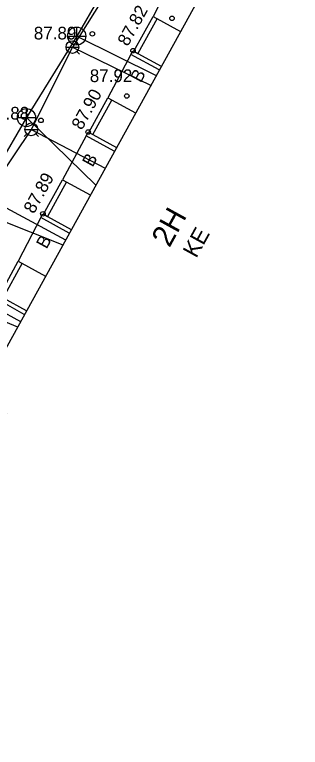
# Model space of a CAD drawing. Extents: x 648748 to 649126, y 6457789 to 6458252.
# Drawn here: x 648855.94 to 648871.67, y 6458013.84 to 6458054.26 of the extents above; entities that cross this region are included whole.
import ezdxf

# ---------------------------------------------------------------- set-up
doc = ezdxf.new("R2010")
doc.units = 0
for name, color, linetype in [('HOONE', 7, 'Continuous'), ('HOONEDET', 7, 'Continuous'), ('KKAEV', 7, 'Continuous'), ('KORGUS-EH2000', 7, 'Continuous'), ('KTRASS', 7, 'Continuous'), ('TEE', 7, 'Continuous'), ('VKAEV', 7, 'Continuous'), ('VTRASS', 7, 'Continuous')]:
    doc.layers.add(name, color=color, linetype=linetype)

msp = doc.modelspace()

# ---------------------------------------------------------------- linework, layer by layer
at = {"layer": 'HOONE'}
for points in [[(648871.67, 6458059.037), (648869.02, 6458060.498), (648853.919, 6458033.105), (648855.485, 6458032.242), (648840.687, 6458005.398), (648842.333, 6458004.491), (648827.567, 6457977.705), (648832.374, 6457975.097)], [(648863.896, 6458051.204), (648862.339, 6458052.062), (648862.452, 6458052.267), (648862.503, 6458052.239), (648863.562, 6458054.16), (648865.068, 6458053.33)], [(648861.425, 6458046.721), (648859.873, 6458047.576), (648859.986, 6458047.781), (648860.024, 6458047.76), (648861.074, 6458049.666), (648862.589, 6458048.832)], [(648858.938, 6458042.209), (648857.38, 6458043.068), (648857.493, 6458043.273), (648857.534, 6458043.25), (648858.581, 6458045.15), (648860.098, 6458044.313)], [(648856.466, 6458037.725), (648854.897, 6458038.59), (648855.01, 6458038.795), (648855.085, 6458038.754), (648856.136, 6458040.661), (648857.631, 6458039.837)]]:
    msp.add_lwpolyline(points, dxfattribs=at)
at = {"layer": 'HOONEDET'}
for p, q in [((648863.781, 6458054.039), (648862.722, 6458052.118)), ((648860.243, 6458047.64), (648861.293, 6458049.546)), ((648858.8, 6458045.029), (648857.753, 6458043.13)), ((648856.355, 6458040.541), (648855.304, 6458038.633))]:
    msp.add_line(p, q, dxfattribs=at)
for points in [[(648862.503, 6458052.239), (648862.722, 6458052.118), (648864.009, 6458051.408)], [(648860.024, 6458047.76), (648860.243, 6458047.64), (648861.538, 6458046.925)], [(648857.534, 6458043.25), (648857.753, 6458043.13), (648859.051, 6458042.414)], [(648855.085, 6458038.754), (648855.304, 6458038.633), (648856.579, 6458037.93)]]:
    msp.add_lwpolyline(points, dxfattribs=at)
at = {"layer": 'KKAEV'}
for p, q in [((648859.355, 6458052.572), (648859.355, 6458053.572)), ((648858.855, 6458053.072), (648859.855, 6458053.072)), ((648856.587, 6458048.075), (648856.587, 6458049.075)), ((648856.087, 6458048.575), (648857.087, 6458048.575))]:
    msp.add_line(p, q, dxfattribs=at)
for centre in [(648859.355, 6458053.072), (648856.587, 6458048.575)]:
    msp.add_circle(centre, 0.5, dxfattribs=at)
at = {"layer": 'KORGUS-EH2000'}
for centre in [(648864.603, 6458054.053), (648860.215, 6458053.2), (648862.452, 6458052.267), (648862.112, 6458049.769), (648857.384, 6458048.423), (648859.986, 6458047.781), (648857.493, 6458043.273)]:
    msp.add_circle(centre, 0.125, dxfattribs=at)
at = {"layer": 'KTRASS'}
for p, q in [((648861.722, 6458057.158), (648859.355, 6458053.072)), ((648859.355, 6458053.072), (648856.587, 6458048.575)), ((648859.355, 6458053.072), (648863.723, 6458050.903)), ((648856.587, 6458048.575), (648854.114, 6458044.329)), ((648856.587, 6458048.575), (648860.4, 6458044.844)), ((648854.114, 6458044.329), (648858.745, 6458041.841)), ((648851.641, 6458039.895), (648856.255, 6458037.322))]:
    msp.add_line(p, q, dxfattribs=at)
at = {"layer": 'TEE'}
for p, q in [((648864.782, 6458056.52), (648863.562, 6458054.16)), ((648862.339, 6458052.062), (648861.074, 6458049.666)), ((648859.873, 6458047.576), (648858.581, 6458045.15)), ((648857.38, 6458043.068), (648856.136, 6458040.661))]:
    msp.add_line(p, q, dxfattribs=at)
at = {"layer": 'VKAEV'}
for p, q in [((648858.871, 6458052.221), (648858.732, 6458052.082)), ((648858.769, 6458052.469), (648859.469, 6458052.469)), ((648859.366, 6458052.221), (648859.506, 6458052.082)), ((648856.505, 6458047.93), (648857.205, 6458047.93)), ((648856.608, 6458047.683), (648856.468, 6458047.543)), ((648857.103, 6458047.683), (648857.242, 6458047.543))]:
    msp.add_line(p, q, dxfattribs=at)
for centre in [(648859.119, 6458052.469), (648856.855, 6458047.93)]:
    msp.add_circle(centre, 0.35, dxfattribs=at)
at = {"layer": 'VTRASS'}
for p, q in [((648856.855, 6458047.93), (648860.922, 6458045.792)), ((648853.84, 6458043.444), (648858.594, 6458041.566)), ((648851.542, 6458038.91), (648856.099, 6458037.039))]:
    msp.add_line(p, q, dxfattribs=at)
for points in [[(648864.219, 6458061.359), (648861.546, 6458056.334), (648859.119, 6458052.469), (648856.855, 6458047.93), (648853.84, 6458043.444), (648851.542, 6458038.91), (648849.187, 6458034.556), (648847.091, 6458030.397), (648844.237, 6458025.408), (648841.658, 6458021.177), (648839.178, 6458016.45), (648837.21, 6458012.35), (648834.536, 6458007.426), (648832.327, 6458003.249), (648829.651, 6457998.416), (648827.169, 6457994.074), (648824.746, 6457989.896), (648822.496, 6457985.078), (648821.983, 6457983.396), (648822.36, 6457981.31), (648825.099, 6457977.566), (648828.129, 6457973.95), (648829.36, 6457973.21)], [(648859.119, 6458052.469), (648863.449, 6458050.349)]]:
    msp.add_lwpolyline(points, dxfattribs=at)

# ---------------------------------------------------------------- texts
at = {"layer": 'HOONE'}
for s, height, p in [('2H', 1.2, (648864.461, 6458041.367)), ('KE', 0.9, (648865.939, 6458040.784))]:
    msp.add_text(s, height=height, rotation=61.1339, dxfattribs=at).set_placement(p)
at = {"layer": 'KORGUS-EH2000'}
for s, p in [('87.82', (648862.169, 6458052.469)), ('87.90', (648859.636, 6458047.851)), ('87.89', (648856.996, 6458043.232))]:
    msp.add_text(s, height=0.7, rotation=61.1339, dxfattribs=at).set_placement(p)
for s, p in [('87.89', (648856.992, 6458052.887)), ('87.92', (648860.074, 6458050.537)), ('87.88', (648854.394, 6458048.47))]:
    msp.add_text(s, height=0.7, dxfattribs=at).set_placement(p)
at = {"layer": 'TEE'}
for p in [(648862.882, 6458050.461), (648860.229, 6458045.808), (648857.693, 6458041.294)]:
    msp.add_text('B', height=0.7, rotation=61.1339, dxfattribs=at).set_placement(p)

doc.saveas('drawing.dxf')
